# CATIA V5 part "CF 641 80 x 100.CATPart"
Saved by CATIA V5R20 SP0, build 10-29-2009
Part number: CF 641 80 x 100
Definition: NONE
Nomenclature: CF 641 80 x 100
Source: Unknown
Description: CF 641 80 x 100
Bounding box of the stored display mesh (mm): x -52 to 48, y -55.5 to 55.5, z -55.5 to 55.5
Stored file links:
  C:\Users\Utente\Desktop\IO LAVORO\3D X SITO CF\X SITO\CF 641\CF 641 80 x 100.CATPart
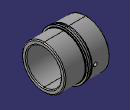
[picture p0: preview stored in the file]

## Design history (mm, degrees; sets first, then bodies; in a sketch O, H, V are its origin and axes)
Body1 "CF 641 80 x 100" (main body)
  Solid1: solid without history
